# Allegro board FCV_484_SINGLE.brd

Outline 347.98 x 322.58 mm; copper layers: TOP, SIG1, SIG2, SIG3, BOTTOM. Coordinates in mm from the lower left corner of the outline.
Outline path: rectangle 0,0 347.98,322.58

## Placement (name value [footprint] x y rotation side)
U1  -  [22X22]  173.99 168.17 0 top

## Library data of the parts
U1 = 22X22_0

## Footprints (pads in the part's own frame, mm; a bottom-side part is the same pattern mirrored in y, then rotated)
22X22
  round 0.401 smd: A1(-8.4,8.4) A2(-7.6,8.4) A3(-6.8,8.4) A4(-5.999,8.4) A5(-5.199,8.4) A6(-4.399,8.4) A7(-3.599,8.4) A8(-2.799,8.4) A9(-1.999,8.4) A10(-1.199,8.4) A11(-0.399,8.4) A12(0.399,8.4) A13(1.199,8.4) A14(1.999,8.4) A15(2.799,8.4) A16(3.599,8.4) A17(4.399,8.4) A18(5.199,8.4) A19(5.999,8.4) A20(6.8,8.4) A21(7.6,8.4) A22(8.4,8.4) AA1(-8.4,-7.6) AA2(-7.6,-7.6) AA3(-6.8,-7.6) AA4(-5.999,-7.6) AA5(-5.199,-7.6) AA6(-4.399,-7.6) AA7(-3.599,-7.6) AA8(-2.799,-7.6) AA9(-1.999,-7.6) AA10(-1.199,-7.6) AA11(-0.399,-7.6) AA12(0.399,-7.6) AA13(1.199,-7.6) AA14(1.999,-7.6) AA15(2.799,-7.6) AA16(3.599,-7.6) AA17(4.399,-7.6) AA18(5.199,-7.6) AA19(5.999,-7.6) AA20(6.8,-7.6) AA21(7.6,-7.6) AA22(8.4,-7.6) AB1(-8.4,-8.4) AB2(-7.6,-8.4) AB3(-6.8,-8.4) AB4(-5.999,-8.4) AB5(-5.199,-8.4) AB6(-4.399,-8.4) AB7(-3.599,-8.4) AB8(-2.799,-8.4) AB9(-1.999,-8.4) AB10(-1.199,-8.4) AB11(-0.399,-8.4) AB12(0.399,-8.4) AB13(1.199,-8.4) AB14(1.999,-8.4) AB15(2.799,-8.4) AB16(3.599,-8.4) AB17(4.399,-8.4) AB18(5.199,-8.4) AB19(5.999,-8.4) AB20(6.8,-8.4) AB21(7.6,-8.4) AB22(8.4,-8.4) B1(-8.4,7.6) B2(-7.6,7.6) B3(-6.8,7.6) B4(-5.999,7.6) B5(-5.199,7.6) B6(-4.399,7.6) B7(-3.599,7.6) B8(-2.799,7.6) B9(-1.999,7.6) B10(-1.199,7.6) B11(-0.399,7.6) B12(0.399,7.6) B13(1.199,7.6) B14(1.999,7.6) B15(2.799,7.6) B16(3.599,7.6) B17(4.399,7.6) B18(5.199,7.6) B19(5.999,7.6) B20(6.8,7.6) B21(7.6,7.6) B22(8.4,7.6) C1(-8.4,6.8) C2(-7.6,6.8) C3(-6.8,6.8) C4(-5.999,6.8) C5(-5.199,6.8) C6(-4.399,6.8) C7(-3.599,6.8) C8(-2.799,6.8) C9(-1.999,6.8) C10(-1.199,6.8) C11(-0.399,6.8) C12(0.399,6.8) C13(1.199,6.8) C14(1.999,6.8) C15(2.799,6.8) C16(3.599,6.8) C17(4.399,6.8) C18(5.199,6.8) C19(5.999,6.8) C20(6.8,6.8) C21(7.6,6.8) C22(8.4,6.8) D1(-8.4,5.999) D2(-7.6,5.999) D3(-6.8,5.999) D4(-5.999,5.999) D5(-5.199,5.999) D6(-4.399,5.999) D7(-3.599,5.999) D8(-2.799,5.999) D9(-1.999,5.999) D10(-1.199,5.999) D11(-0.399,5.999) D12(0.399,5.999) D13(1.199,5.999) D14(1.999,5.999) D15(2.799,5.999) D16(3.599,5.999) D17(4.399,5.999) D18(5.199,5.999) D19(5.999,5.999) D20(6.8,5.999) D21(7.6,5.999) D22(8.4,5.999) E1(-8.4,5.199) E2(-7.6,5.199) E3(-6.8,5.199) E4(-5.999,5.199) E5(-5.199,5.199) E6(-4.399,5.199) E7(-3.599,5.199) E8(-2.799,5.199) E9(-1.999,5.199) E10(-1.199,5.199) E11(-0.399,5.199) E12(0.399,5.199) E13(1.199,5.199) E14(1.999,5.199) E15(2.799,5.199) E16(3.599,5.199) E17(4.399,5.199) E18(5.199,5.199) E19(5.999,5.199) E20(6.8,5.199) E21(7.6,5.199) E22(8.4,5.199) F1(-8.4,4.399) F2(-7.6,4.399) F3(-6.8,4.399) F4(-5.999,4.399) F5(-5.199,4.399) F6(-4.399,4.399) F7(-3.599,4.399) F8(-2.799,4.399) F9(-1.999,4.399) F10(-1.199,4.399) F11(-0.399,4.399) F12(0.399,4.399) F13(1.199,4.399) F14(1.999,4.399) F15(2.799,4.399) F16(3.599,4.399) F17(4.399,4.399) F18(5.199,4.399) F19(5.999,4.399) F20(6.8,4.399) F21(7.6,4.399) F22(8.4,4.399) G1(-8.4,3.599) G2(-7.6,3.599) G3(-6.8,3.599) G4(-5.999,3.599) G5(-5.199,3.599) G6(-4.399,3.599) G7(-3.599,3.599) G8(-2.799,3.599) G9(-1.999,3.599) G10(-1.199,3.599) G11(-0.399,3.599) G12(0.399,3.599) G13(1.199,3.599) G14(1.999,3.599) G15(2.799,3.599) G16(3.599,3.599) G17(4.399,3.599) G18(5.199,3.599) G19(5.999,3.599) G20(6.8,3.599) G21(7.6,3.599) G22(8.4,3.599) H1(-8.4,2.799) H2(-7.6,2.799) H3(-6.8,2.799) H4(-5.999,2.799) H5(-5.199,2.799) H6(-4.399,2.799) H7(-3.599,2.799) H8(-2.799,2.799) H9(-1.999,2.799) H10(-1.199,2.799) H11(-0.399,2.799) H12(0.399,2.799) H13(1.199,2.799) H14(1.999,2.799) H15(2.799,2.799) H16(3.599,2.799) H17(4.399,2.799) H18(5.199,2.799) H19(5.999,2.799) H20(6.8,2.799) H21(7.6,2.799) H22(8.4,2.799) J1(-8.4,1.999) J2(-7.6,1.999) J3(-6.8,1.999) J4(-5.999,1.999) J5(-5.199,1.999) J6(-4.399,1.999) J7(-3.599,1.999) J8(-2.799,1.999) J9(-1.999,1.999) J10(-1.199,1.999) J11(-0.399,1.999) J12(0.399,1.999) J13(1.199,1.999) J14(1.999,1.999) J15(2.799,1.999) J16(3.599,1.999) J17(4.399,1.999) J18(5.199,1.999) J19(5.999,1.999) J20(6.8,1.999) J21(7.6,1.999) J22(8.4,1.999) K1(-8.4,1.199) K2(-7.6,1.199) K3(-6.8,1.199) K4(-5.999,1.199) K5(-5.199,1.199) K6(-4.399,1.199) K7(-3.599,1.199) K8(-2.799,1.199) K9(-1.999,1.199) K10(-1.199,1.199) K11(-0.399,1.199) K12(0.399,1.199) K13(1.199,1.199) K14(1.999,1.199) K15(2.799,1.199) K16(3.599,1.199) K17(4.399,1.199) K18(5.199,1.199) K19(5.999,1.199) K20(6.8,1.199) K21(7.6,1.199) K22(8.4,1.199) L1(-8.4,0.399) L2(-7.6,0.399) L3(-6.8,0.399) L4(-5.999,0.399) L5(-5.199,0.399) L6(-4.399,0.399) L7(-3.599,0.399) L8(-2.799,0.399) L9(-1.999,0.399) L10(-1.199,0.399) L11(-0.399,0.399) L12(0.399,0.399) L13(1.199,0.399) L14(1.999,0.399) L15(2.799,0.399) L16(3.599,0.399) L17(4.399,0.399) L18(5.199,0.399) L19(5.999,0.399) L20(6.8,0.399) L21(7.6,0.399) L22(8.4,0.399) M1(-8.4,-0.399) M2(-7.6,-0.399) M3(-6.8,-0.399) M4(-5.999,-0.399) M5(-5.199,-0.399) M6(-4.399,-0.399) M7(-3.599,-0.399) M8(-2.799,-0.399) M9(-1.999,-0.399) M10(-1.199,-0.399) M11(-0.399,-0.399) M12(0.399,-0.399) M13(1.199,-0.399) M14(1.999,-0.399) M15(2.799,-0.399) M16(3.599,-0.399) M17(4.399,-0.399) M18(5.199,-0.399) M19(5.999,-0.399) M20(6.8,-0.399) M21(7.6,-0.399) M22(8.4,-0.399) N1(-8.4,-1.199) N2(-7.6,-1.199) N3(-6.8,-1.199) N4(-5.999,-1.199) N5(-5.199,-1.199) N6(-4.399,-1.199) N7(-3.599,-1.199) N8(-2.799,-1.199) N9(-1.999,-1.199) N10(-1.199,-1.199) N11(-0.399,-1.199) N12(0.399,-1.199) N13(1.199,-1.199) N14(1.999,-1.199) N15(2.799,-1.199) N16(3.599,-1.199) N17(4.399,-1.199) N18(5.199,-1.199) N19(5.999,-1.199) N20(6.8,-1.199) N21(7.6,-1.199) N22(8.4,-1.199) P1(-8.4,-1.999) P2(-7.6,-1.999) P3(-6.8,-1.999) P4(-5.999,-1.999) P5(-5.199,-1.999) P6(-4.399,-1.999) P7(-3.599,-1.999) P8(-2.799,-1.999) P9(-1.999,-1.999) P10(-1.199,-1.999) P11(-0.399,-1.999) P12(0.399,-1.999) P13(1.199,-1.999) P14(1.999,-1.999) P15(2.799,-1.999) P16(3.599,-1.999) P17(4.399,-1.999) P18(5.199,-1.999) P19(5.999,-1.999) P20(6.8,-1.999) P21(7.6,-1.999) P22(8.4,-1.999) R1(-8.4,-2.799) R2(-7.6,-2.799) R3(-6.8,-2.799) R4(-5.999,-2.799) R5(-5.199,-2.799) R6(-4.399,-2.799) R7(-3.599,-2.799) R8(-2.799,-2.799) R9(-1.999,-2.799) R10(-1.199,-2.799) R11(-0.399,-2.799) R12(0.399,-2.799) R13(1.199,-2.799) R14(1.999,-2.799) R15(2.799,-2.799) R16(3.599,-2.799) R17(4.399,-2.799) R18(5.199,-2.799) R19(5.999,-2.799) R20(6.8,-2.799) R21(7.6,-2.799) R22(8.4,-2.799) T1(-8.4,-3.599) T2(-7.6,-3.599) T3(-6.8,-3.599) T4(-5.999,-3.599) T5(-5.199,-3.599) T6(-4.399,-3.599) T7(-3.599,-3.599) T8(-2.799,-3.599) T9(-1.999,-3.599) T10(-1.199,-3.599) T11(-0.399,-3.599) T12(0.399,-3.599) T13(1.199,-3.599) T14(1.999,-3.599) T15(2.799,-3.599) T16(3.599,-3.599) T17(4.399,-3.599) T18(5.199,-3.599) T19(5.999,-3.599) T20(6.8,-3.599) T21(7.6,-3.599) T22(8.4,-3.599) U1(-8.4,-4.399) U2(-7.6,-4.399) U3(-6.8,-4.399) U4(-5.999,-4.399) U5(-5.199,-4.399) U6(-4.399,-4.399) U7(-3.599,-4.399) U8(-2.799,-4.399) U9(-1.999,-4.399) U10(-1.199,-4.399) U11(-0.399,-4.399) U12(0.399,-4.399) U13(1.199,-4.399) U14(1.999,-4.399) U15(2.799,-4.399) U16(3.599,-4.399) U17(4.399,-4.399) U18(5.199,-4.399) U19(5.999,-4.399) U20(6.8,-4.399) U21(7.6,-4.399) U22(8.4,-4.399) V1(-8.4,-5.199) V2(-7.6,-5.199) V3(-6.8,-5.199) V4(-5.999,-5.199) V5(-5.199,-5.199) V6(-4.399,-5.199) V7(-3.599,-5.199) V8(-2.799,-5.199) V9(-1.999,-5.199) V10(-1.199,-5.199) V11(-0.399,-5.199) V12(0.399,-5.199) V13(1.199,-5.199) V14(1.999,-5.199) V15(2.799,-5.199) V16(3.599,-5.199) V17(4.399,-5.199) V18(5.199,-5.199) V19(5.999,-5.199) V20(6.8,-5.199) V21(7.6,-5.199) V22(8.4,-5.199) W1(-8.4,-5.999) W2(-7.6,-5.999) W3(-6.8,-5.999) W4(-5.999,-5.999) W5(-5.199,-5.999) W6(-4.399,-5.999) W7(-3.599,-5.999) W8(-2.799,-5.999) W9(-1.999,-5.999) W10(-1.199,-5.999) W11(-0.399,-5.999) W12(0.399,-5.999) W13(1.199,-5.999) W14(1.999,-5.999) W15(2.799,-5.999) W16(3.599,-5.999) W17(4.399,-5.999) W18(5.199,-5.999) W19(5.999,-5.999) W20(6.8,-5.999) W21(7.6,-5.999) W22(8.4,-5.999) Y1(-8.4,-6.8) Y2(-7.6,-6.8) Y3(-6.8,-6.8) Y4(-5.999,-6.8) Y5(-5.199,-6.8) Y6(-4.399,-6.8) Y7(-3.599,-6.8) Y8(-2.799,-6.8) Y9(-1.999,-6.8) Y10(-1.199,-6.8) Y11(-0.399,-6.8) Y12(0.399,-6.8) Y13(1.199,-6.8) Y14(1.999,-6.8) Y15(2.799,-6.8) Y16(3.599,-6.8) Y17(4.399,-6.8) Y18(5.199,-6.8) Y19(5.999,-6.8) Y20(6.8,-6.8) Y21(7.6,-6.8) Y22(8.4,-6.8)

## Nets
VDD: U1.J13(VDD#J13) U1.K12(VDD#K12) U1.K14(VDD#K14) U1.K16(VDD#K16) U1.L11(VDD#L11) U1.L15(VDD#L15) U1.L17(VDD#L17) U1.M12(VDD#M12) U1.M14(VDD#M14) U1.M16(VDD#M16) U1.N11(VDD#N11) U1.N13(VDD#N13) U1.N15(VDD#N15) U1.N17(VDD#N17)
VDD18: U1.N14(VDD18#N14) U1.P10(VDD18#P10) U1.P12(VDD18#P12) U1.P14(VDD18#P14) U1.P16(VDD18#P16)
VDD25: U1.H8(VDD25#H8) U1.J17(VDD25#J17) U1.L13(VDD25#L13) U1.R9(VDD25#R9) U1.R17(VDD25#R17)
VDDA: U1.G21(VDDA#G21) U1.J21(VDDA#J21) U1.K19(VDDA#K19) U1.L21(VDDA#L21) U1.N21(VDDA#N21) U1.P19(VDDA#P19) U1.R21(VDDA#R21)
VDDA25: U1.J18(VDDA25#J18) U1.N18(VDDA25#N18)
VDDAUX2: U1.H11(VDDAUX2#H11) U1.H14(VDDAUX2#H14) U1.H16(VDDAUX2#H16) U1.J15(VDDAUX2#J15)
VDDAUX4: U1.F4(VDDAUX4#F4) U1.G1(VDDAUX4#G1) U1.K10(VDDAUX4#K10) U1.M10(VDDAUX4#M10) U1.N9(VDDAUX4#N9)
VDDI0: U1.AA9(VDDI0#AA9) U1.AB6(VDDI0#AB6) U1.U1(VDDI0#U1) U1.U11(VDDI0#U11) U1.V8(VDDI0#V8) U1.W5(VDDI0#W5) U1.Y2(VDDI0#Y2)
VDDI1: U1.AA19(VDDI1#AA19) U1.AB16(VDDI1#AB16) U1.T14(VDDI1#T14) U1.V18(VDDI1#V18) U1.W15(VDDI1#W15) U1.Y12(VDDI1#Y12) U1.Y22(VDDI1#Y22)
VDDI2: U1.A9(VDDI2#A9) U1.A19(VDDI2#A19) U1.B6(VDDI2#B6) U1.B16(VDDI2#B16) U1.C3(VDDI2#C3) U1.C13(VDDI2#C13) U1.C21(VDDI2#C21) U1.D10(VDDI2#D10) U1.E7(VDDI2#E7) U1.E17(VDDI2#E17) U1.F14(VDDI2#F14) U1.H13(VDDI2#H13) U1.H17(VDDI2#H17)
VDDI3: U1.G11(VDDI3#G11) U1.J11(VDDI3#J11)
VDDI4: U1.J5(VDDI4#J5) U1.K2(VDDI4#K2) U1.L9(VDDI4#L9) U1.M6(VDDI4#M6) U1.N3(VDDI4#N3) U1.R7(VDDI4#R7) U1.T4(VDDI4#T4)
VDDSREF: U1.L18(VDDSREF#L18) U1.R18(VDDSREF#R18)
VSS: U1.A1(VSS#A1) U1.A4(VSS#A4) U1.A14(VSS#A14) U1.A22(VSS#A22) U1.AA4(VSS#AA4) U1.AA14(VSS#AA14) U1.AB1(VSS#AB1) U1.AB11(VSS#AB11) U1.AB22(VSS#AB22) U1.B11(VSS#B11) U1.C8(VSS#C8) U1.C18(VSS#C18) U1.D5(VSS#D5) U1.D15(VSS#D15) U1.E2(VSS#E2) U1.E12(VSS#E12) U1.F9(VSS#F9) U1.G6(VSS#G6) U1.G16(VSS#G16) U1.H3(VSS#H3) U1.J10(VSS#J10) U1.J12(VSS#J12) U1.J14(VSS#J14) U1.J16(VSS#J16) U1.K7(VSS#K7) U1.K11(VSS#K11) U1.K13(VSS#K13) U1.K15(VSS#K15) U1.K17(VSS#K17) U1.L4(VSS#L4) U1.L10(VSS#L10) U1.L12(VSS#L12) U1.L14(VSS#L14) U1.L16(VSS#L16) U1.M1(VSS#M1) U1.M11(VSS#M11) U1.M13(VSS#M13) U1.M15(VSS#M15) U1.M17(VSS#M17) U1.N10(VSS#N10) U1.N12(VSS#N12) U1.N16(VSS#N16) U1.P5(VSS#P5) U1.P11(VSS#P11) U1.P13(VSS#P13) U1.P15(VSS#P15) U1.P17(VSS#P17) U1.R2(VSS#R2) U1.T9(VSS#T9) U1.U6(VSS#U6) U1.U16(VSS#U16) U1.V3(VSS#V3) U1.V13(VSS#V13) U1.W10(VSS#W10) U1.W20(VSS#W20) U1.Y7(VSS#Y7) U1.Y17(VSS#Y17)
VSSA: U1.E20(VSSA#E20) U1.E21(VSSA#E21) U1.E22(VSSA#E22) U1.F18(VSSA#F18) U1.F19(VSSA#F19) U1.F20(VSSA#F20) U1.G18(VSSA#G18) U1.G22(VSSA#G22) U1.H20(VSSA#H20) U1.J22(VSSA#J22) U1.K18(VSSA#K18) U1.K20(VSSA#K20) U1.L22(VSSA#L22) U1.M18(VSSA#M18) U1.M19(VSSA#M19) U1.M20(VSSA#M20) U1.N22(VSSA#N22) U1.P18(VSSA#P18) U1.P20(VSSA#P20) U1.R22(VSSA#R22) U1.T18(VSSA#T18) U1.T19(VSSA#T19) U1.T20(VSSA#T20) U1.U20(VSSA#U20) U1.U21(VSSA#U21) U1.U22(VSSA#U22)
IO-BANK0_1: U1.R10(IO-BANK0_1)
IO-BANK0_2: U1.R11(IO-BANK0_2)
IO-BANK0_3: U1.R12(IO-BANK0_3)
IO-BANK0_4: U1.T6(IO-BANK0_4)
IO-BANK0_5: U1.T7(IO-BANK0_5)
IO-BANK0_6: U1.T8(IO-BANK0_6)
IO-BANK0_7: U1.T10(IO-BANK0_7)
IO-BANK0_8: U1.T11(IO-BANK0_8)
IO-BANK0_9: U1.U2(IO-BANK0_9)
IO-BANK0_10: U1.U3(IO-BANK0_10)
IO-BANK0_11: U1.U4(IO-BANK0_11)
IO-BANK0_12: U1.U5(IO-BANK0_12)
IO-BANK0_13: U1.U7(IO-BANK0_13)
IO-BANK0_14: U1.U8(IO-BANK0_14)
IO-BANK0_15: U1.U9(IO-BANK0_15)
IO-BANK0_16: U1.U10(IO-BANK0_16)
IO-BANK0_17: U1.V1(IO-BANK0_17)
IO-BANK0_18: U1.V2(IO-BANK0_18)
IO-BANK0_19: U1.V4(IO-BANK0_19)
IO-BANK0_20: U1.V5(IO-BANK0_20)
IO-BANK0_21: U1.V6(IO-BANK0_21)
IO-BANK0_22: U1.V7(IO-BANK0_22)
IO-BANK0_23: U1.V9(IO-BANK0_23)
IO-BANK0_24: U1.V10(IO-BANK0_24)
IO-BANK0_25: U1.V11(IO-BANK0_25)
IO-BANK0_26: U1.W1(IO-BANK0_26)
IO-BANK0_27: U1.W2(IO-BANK0_27)
IO-BANK0_28: U1.W3(IO-BANK0_28)
IO-BANK0_29: U1.W4(IO-BANK0_29)
IO-BANK0_30: U1.W6(IO-BANK0_30)
IO-BANK0_31: U1.W7(IO-BANK0_31)
IO-BANK0_32: U1.W8(IO-BANK0_32)
IO-BANK0_33: U1.W9(IO-BANK0_33)
IO-BANK0_34: U1.W11(IO-BANK0_34)
IO-BANK0_35: U1.Y1(IO-BANK0_35)
IO-BANK0_36: U1.Y3(IO-BANK0_36)
IO-BANK0_37: U1.Y4(IO-BANK0_37)
IO-BANK0_38: U1.Y5(IO-BANK0_38)
IO-BANK0_39: U1.Y6(IO-BANK0_39)
IO-BANK0_40: U1.Y8(IO-BANK0_40)
IO-BANK0_41: U1.Y9(IO-BANK0_41)
IO-BANK0_42: U1.Y10(IO-BANK0_42)
IO-BANK0_43: U1.Y11(IO-BANK0_43)
IO-BANK0_44: U1.AA1(IO-BANK0_44)
IO-BANK0_45: U1.AA2(IO-BANK0_45)
IO-BANK0_46: U1.AA3(IO-BANK0_46)
IO-BANK0_47: U1.AA5(IO-BANK0_47)
IO-BANK0_48: U1.AA6(IO-BANK0_48)
IO-BANK0_49: U1.AA7(IO-BANK0_49)
IO-BANK0_50: U1.AA8(IO-BANK0_50)
IO-BANK0_51: U1.AA10(IO-BANK0_51)
IO-BANK0_52: U1.AA11(IO-BANK0_52)
IO-BANK0_53: U1.AB2(IO-BANK0_53)
IO-BANK0_54: U1.AB3(IO-BANK0_54)
IO-BANK0_55: U1.AB4(IO-BANK0_55)
IO-BANK0_56: U1.AB5(IO-BANK0_56)
IO-BANK0_57: U1.AB7(IO-BANK0_57)
IO-BANK0_58: U1.AB8(IO-BANK0_58)
IO-BANK0_59: U1.AB9(IO-BANK0_59)
IO-BANK0_60: U1.AB10(IO-BANK0_60)
IO-BANK1_1: U1.R13(IO-BANK1_1)
IO-BANK1_2: U1.R14(IO-BANK1_2)
IO-BANK1_3: U1.R15(IO-BANK1_3)
IO-BANK1_4: U1.R16(IO-BANK1_4)
IO-BANK1_5: U1.T12(IO-BANK1_5)
IO-BANK1_6: U1.T13(IO-BANK1_6)
IO-BANK1_7: U1.T15(IO-BANK1_7)
IO-BANK1_8: U1.T16(IO-BANK1_8)
IO-BANK1_9: U1.T17(IO-BANK1_9)
IO-BANK1_10: U1.U12(IO-BANK1_10)
IO-BANK1_11: U1.U13(IO-BANK1_11)
IO-BANK1_12: U1.U14(IO-BANK1_12)
IO-BANK1_13: U1.U15(IO-BANK1_13)
IO-BANK1_14: U1.U17(IO-BANK1_14)
IO-BANK1_15: U1.U18(IO-BANK1_15)
IO-BANK1_16: U1.U19(IO-BANK1_16)
IO-BANK1_17: U1.V12(IO-BANK1_17)
IO-BANK1_18: U1.V14(IO-BANK1_18)
IO-BANK1_19: U1.V15(IO-BANK1_19)
IO-BANK1_20: U1.V16(IO-BANK1_20)
IO-BANK1_21: U1.V17(IO-BANK1_21)
IO-BANK1_22: U1.V19(IO-BANK1_22)
IO-BANK1_23: U1.V20(IO-BANK1_23)
IO-BANK1_24: U1.V21(IO-BANK1_24)
IO-BANK1_25: U1.V22(IO-BANK1_25)
IO-BANK1_26: U1.W12(IO-BANK1_26)
IO-BANK1_27: U1.W13(IO-BANK1_27)
IO-BANK1_28: U1.W14(IO-BANK1_28)
IO-BANK1_29: U1.W16(IO-BANK1_29)
IO-BANK1_30: U1.W17(IO-BANK1_30)
IO-BANK1_31: U1.W18(IO-BANK1_31)
IO-BANK1_32: U1.W19(IO-BANK1_32)
IO-BANK1_33: U1.W21(IO-BANK1_33)
IO-BANK1_34: U1.W22(IO-BANK1_34)
IO-BANK1_35: U1.Y13(IO-BANK1_35)
IO-BANK1_36: U1.Y14(IO-BANK1_36)
IO-BANK1_37: U1.Y15(IO-BANK1_37)
IO-BANK1_38: U1.Y16(IO-BANK1_38)
IO-BANK1_39: U1.Y18(IO-BANK1_39)
IO-BANK1_40: U1.Y19(IO-BANK1_40)
IO-BANK1_41: U1.Y20(IO-BANK1_41)
IO-BANK1_42: U1.Y21(IO-BANK1_42)
IO-BANK1_43: U1.AA12(IO-BANK1_43)
IO-BANK1_44: U1.AA13(IO-BANK1_44)
IO-BANK1_45: U1.AA15(IO-BANK1_45)
IO-BANK1_46: U1.AA16(IO-BANK1_46)
IO-BANK1_47: U1.AA17(IO-BANK1_47)
IO-BANK1_48: U1.AA18(IO-BANK1_48)
IO-BANK1_49: U1.AA20(IO-BANK1_49)
IO-BANK1_50: U1.AA21(IO-BANK1_50)
IO-BANK1_51: U1.AA22(IO-BANK1_51)
IO-BANK1_52: U1.AB12(IO-BANK1_52)
IO-BANK1_53: U1.AB13(IO-BANK1_53)
IO-BANK1_54: U1.AB14(IO-BANK1_54)
IO-BANK1_55: U1.AB15(IO-BANK1_55)
IO-BANK1_56: U1.AB17(IO-BANK1_56)
IO-BANK1_57: U1.AB18(IO-BANK1_57)
IO-BANK1_58: U1.AB19(IO-BANK1_58)
IO-BANK1_59: U1.AB20(IO-BANK1_59)
IO-BANK1_60: U1.AB21(IO-BANK1_60)
IO-BANK2_1: U1.A2(IO-BANK2_1)
IO-BANK2_2: U1.A3(IO-BANK2_2)
IO-BANK2_3: U1.A5(IO-BANK2_3)
IO-BANK2_4: U1.A6(IO-BANK2_4)
IO-BANK2_5: U1.A7(IO-BANK2_5)
IO-BANK2_6: U1.A8(IO-BANK2_6)
IO-BANK2_7: U1.A10(IO-BANK2_7)
IO-BANK2_8: U1.A11(IO-BANK2_8)
IO-BANK2_9: U1.A12(IO-BANK2_9)
IO-BANK2_10: U1.A13(IO-BANK2_10)
IO-BANK2_11: U1.A15(IO-BANK2_11)
IO-BANK2_12: U1.A16(IO-BANK2_12)
IO-BANK2_13: U1.A17(IO-BANK2_13)
IO-BANK2_14: U1.A18(IO-BANK2_14)
IO-BANK2_15: U1.A20(IO-BANK2_15)
IO-BANK2_16: U1.A21(IO-BANK2_16)
IO-BANK2_17: U1.B1(IO-BANK2_17)
IO-BANK2_18: U1.B2(IO-BANK2_18)
IO-BANK2_19: U1.B3(IO-BANK2_19)
IO-BANK2_20: U1.B4(IO-BANK2_20)
IO-BANK2_21: U1.B5(IO-BANK2_21)
IO-BANK2_22: U1.B7(IO-BANK2_22)
IO-BANK2_23: U1.B8(IO-BANK2_23)
IO-BANK2_24: U1.B9(IO-BANK2_24)
IO-BANK2_25: U1.B10(IO-BANK2_25)
IO-BANK2_26: U1.B12(IO-BANK2_26)
IO-BANK2_27: U1.B13(IO-BANK2_27)
IO-BANK2_28: U1.B14(IO-BANK2_28)
IO-BANK2_29: U1.B15(IO-BANK2_29)
IO-BANK2_30: U1.B17(IO-BANK2_30)
IO-BANK2_31: U1.B18(IO-BANK2_31)
IO-BANK2_32: U1.B19(IO-BANK2_32)
IO-BANK2_33: U1.B20(IO-BANK2_33)
IO-BANK2_34: U1.B21(IO-BANK2_34)
IO-BANK2_35: U1.B22(IO-BANK2_35)
IO-BANK2_36: U1.C1(IO-BANK2_36)
IO-BANK2_37: U1.C2(IO-BANK2_37)
IO-BANK2_38: U1.C4(IO-BANK2_38)
IO-BANK2_39: U1.C5(IO-BANK2_39)
IO-BANK2_40: U1.C6(IO-BANK2_40)
IO-BANK2_41: U1.C7(IO-BANK2_41)
IO-BANK2_42: U1.C9(IO-BANK2_42)
IO-BANK2_43: U1.C10(IO-BANK2_43)
IO-BANK2_44: U1.C11(IO-BANK2_44)
IO-BANK2_45: U1.C12(IO-BANK2_45)
IO-BANK2_46: U1.C14(IO-BANK2_46)
IO-BANK2_47: U1.C15(IO-BANK2_47)
IO-BANK2_48: U1.C16(IO-BANK2_48)
IO-BANK2_49: U1.C17(IO-BANK2_49)
IO-BANK2_50: U1.C19(IO-BANK2_50)
IO-BANK2_51: U1.C20(IO-BANK2_51)
IO-BANK2_52: U1.C22(IO-BANK2_52)
IO-BANK2_53: U1.D3(IO-BANK2_53)
IO-BANK2_54: U1.D4(IO-BANK2_54)
IO-BANK2_55: U1.D6(IO-BANK2_55)
IO-BANK2_56: U1.D7(IO-BANK2_56)
IO-BANK2_57: U1.D8(IO-BANK2_57)
IO-BANK2_58: U1.D9(IO-BANK2_58)
IO-BANK2_59: U1.D11(IO-BANK2_59)
IO-BANK2_60: U1.D12(IO-BANK2_60)
IO-BANK2_61: U1.D13(IO-BANK2_61)
IO-BANK2_62: U1.D14(IO-BANK2_62)
IO-BANK2_63: U1.D16(IO-BANK2_63)
IO-BANK2_64: U1.D17(IO-BANK2_64)
IO-BANK2_65: U1.D18(IO-BANK2_65)
IO-BANK2_66: U1.D19(IO-BANK2_66)
IO-BANK2_67: U1.D20(IO-BANK2_67)
IO-BANK2_68: U1.D21(IO-BANK2_68)
IO-BANK2_69: U1.D22(IO-BANK2_69)
IO-BANK2_70: U1.E4(IO-BANK2_70)
IO-BANK2_71: U1.E5(IO-BANK2_71)
IO-BANK2_72: U1.E6(IO-BANK2_72)
IO-BANK2_73: U1.E8(IO-BANK2_73)
IO-BANK2_74: U1.E9(IO-BANK2_74)
IO-BANK2_75: U1.E10(IO-BANK2_75)
IO-BANK2_76: U1.E11(IO-BANK2_76)
IO-BANK2_77: U1.E13(IO-BANK2_77)
IO-BANK2_78: U1.E14(IO-BANK2_78)
IO-BANK2_79: U1.E15(IO-BANK2_79)
IO-BANK2_80: U1.E16(IO-BANK2_80)
IO-BANK2_81: U1.E18(IO-BANK2_81)
IO-BANK2_82: U1.E19(IO-BANK2_82)
IO-BANK2_83: U1.F10(IO-BANK2_83)
IO-BANK2_84: U1.F11(IO-BANK2_84)
IO-BANK2_85: U1.F12(IO-BANK2_85)
IO-BANK2_86: U1.F13(IO-BANK2_86)
IO-BANK2_87: U1.F15(IO-BANK2_87)
IO-BANK2_88: U1.F16(IO-BANK2_88)
IO-BANK2_89: U1.F17(IO-BANK2_89)
IO-BANK2_90: U1.G12(IO-BANK2_90)
IO-BANK2_91: U1.G13(IO-BANK2_91)
IO-BANK2_92: U1.G14(IO-BANK2_92)
IO-BANK2_93: U1.G15(IO-BANK2_93)
IO-BANK2_94: U1.G17(IO-BANK2_94)
IO-BANK2_95: U1.H12(IO-BANK2_95)
IO-BANK2_96: U1.H15(IO-BANK2_96)
IO-BANK4_1: U1.H1(IO-BANK4_1)
IO-BANK4_2: U1.H2(IO-BANK4_2)
IO-BANK4_3: U1.J1(IO-BANK4_3)
IO-BANK4_4: U1.J2(IO-BANK4_4)
IO-BANK4_5: U1.J3(IO-BANK4_5)
IO-BANK4_6: U1.J4(IO-BANK4_6)
IO-BANK4_7: U1.J6(IO-BANK4_7)
IO-BANK4_8: U1.J7(IO-BANK4_8)
IO-BANK4_9: U1.J8(IO-BANK4_9)
IO-BANK4_10: U1.J9(IO-BANK4_10)
IO-BANK4_11: U1.K1(IO-BANK4_11)
IO-BANK4_12: U1.K3(IO-BANK4_12)
IO-BANK4_13: U1.K4(IO-BANK4_13)
IO-BANK4_14: U1.K5(IO-BANK4_14)
IO-BANK4_15: U1.K6(IO-BANK4_15)
IO-BANK4_16: U1.K8(IO-BANK4_16)
IO-BANK4_17: U1.K9(IO-BANK4_17)
IO-BANK4_18: U1.L1(IO-BANK4_18)
IO-BANK4_19: U1.L2(IO-BANK4_19)
IO-BANK4_20: U1.L3(IO-BANK4_20)
IO-BANK4_21: U1.L5(IO-BANK4_21)
IO-BANK4_22: U1.L6(IO-BANK4_22)
IO-BANK4_23: U1.L7(IO-BANK4_23)
IO-BANK4_24: U1.L8(IO-BANK4_24)
IO-BANK4_25: U1.M2(IO-BANK4_25)
IO-BANK4_26: U1.M3(IO-BANK4_26)
IO-BANK4_27: U1.M4(IO-BANK4_27)
IO-BANK4_28: U1.M5(IO-BANK4_28)
IO-BANK4_29: U1.M7(IO-BANK4_29)
IO-BANK4_30: U1.M8(IO-BANK4_30)
IO-BANK4_31: U1.M9(IO-BANK4_31)
IO-BANK4_32: U1.N1(IO-BANK4_32)
IO-BANK4_33: U1.N2(IO-BANK4_33)
IO-BANK4_34: U1.N4(IO-BANK4_34)
IO-BANK4_35: U1.N5(IO-BANK4_35)
IO-BANK4_36: U1.N6(IO-BANK4_36)
IO-BANK4_37: U1.N7(IO-BANK4_37)
IO-BANK4_38: U1.N8(IO-BANK4_38)
IO-BANK4_39: U1.P1(IO-BANK4_39)
IO-BANK4_40: U1.P2(IO-BANK4_40)
IO-BANK4_41: U1.P3(IO-BANK4_41)
IO-BANK4_42: U1.P4(IO-BANK4_42)
IO-BANK4_43: U1.P6(IO-BANK4_43)
IO-BANK4_44: U1.P7(IO-BANK4_44)
IO-BANK4_45: U1.P8(IO-BANK4_45)
IO-BANK4_46: U1.P9(IO-BANK4_46)
IO-BANK4_47: U1.R1(IO-BANK4_47)
IO-BANK4_48: U1.R3(IO-BANK4_48)
IO-BANK4_49: U1.R4(IO-BANK4_49)
IO-BANK4_50: U1.R5(IO-BANK4_50)
IO-BANK4_51: U1.R6(IO-BANK4_51)
IO-BANK4_52: U1.R8(IO-BANK4_52)
IO-BANK4_53: U1.T1(IO-BANK4_53)
IO-BANK4_54: U1.T2(IO-BANK4_54)
IO-BANK4_55: U1.T3(IO-BANK4_55)
IO-BANK4_56: U1.T5(IO-BANK4_56)
IO-BANK5_1: U1.D1(IO-BANK5_1)
IO-BANK5_2: U1.D2(IO-BANK5_2)
IO-BANK5_3: U1.E1(IO-BANK5_3)
IO-BANK5_4: U1.E3(IO-BANK5_4)
IO-BANK5_5: U1.F1(IO-BANK5_5)
IO-BANK5_6: U1.F2(IO-BANK5_6)
IO-BANK5_7: U1.F3(IO-BANK5_7)
IO-BANK5_8: U1.F5(IO-BANK5_8)
IO-BANK5_9: U1.G2(IO-BANK5_9)
IO-BANK5_10: U1.G3(IO-BANK5_10)
IO-BANK5_11: U1.G4(IO-BANK5_11)
IO-BANK5_12: U1.G5(IO-BANK5_12)
JTAG-IO_1: U1.F6(JTAG-IO_1)
JTAG-IO_2: U1.F7(JTAG-IO_2)
JTAG-IO_3: U1.F8(JTAG-IO_3)
JTAG-IO_4: U1.G7(JTAG-IO_4)
JTAG-IO_5: U1.G8(JTAG-IO_5)
JTAG-IO_6: U1.G9(JTAG-IO_6)
JTAG-IO_7: U1.G10(JTAG-IO_7)
JTAG-IO_8: U1.H4(JTAG-IO_8)
JTAG-IO_9: U1.H5(JTAG-IO_9)
JTAG-IO_10: U1.H6(JTAG-IO_10)
JTAG-IO_11: U1.H7(JTAG-IO_11)
JTAG-IO_12: U1.H9(JTAG-IO_12)
JTAG-IO_13: U1.H10(JTAG-IO_13)
REFCLK0_1: U1.N19(REFCLK0_1)
REFCLK0_2: U1.N20(REFCLK0_2)
REFCLK1_1: U1.L19(REFCLK1_1)
REFCLK1_2: U1.L20(REFCLK1_2)
REFCLK2_1: U1.J19(REFCLK2_1)
REFCLK2_2: U1.J20(REFCLK2_2)
RX0_1: U1.R19(RX0_1)
RX0_2: U1.R20(RX0_2)
RX1_1: U1.M21(RX1_1)
RX1_2: U1.M22(RX1_2)
RX2_1: U1.K21(RX2_1)
RX2_2: U1.K22(RX2_2)
RX3_1: U1.G19(RX3_1)
RX3_2: U1.G20(RX3_2)
SERDES_VREF: U1.H18(SERDES_VREF#H18) U1.H19(SERDES_VREF#H19)
TX0_1: U1.T21(TX0_1)
TX0_2: U1.T22(TX0_2)
TX1_1: U1.P21(TX1_1)
TX1_2: U1.P22(TX1_2)
TX2_1: U1.H21(TX2_1)
TX2_2: U1.H22(TX2_2)
TX3_1: U1.F21(TX3_1)
TX3_2: U1.F22(TX3_2)

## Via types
v1: diameter 0.457, hole 0.254, TOP to BOTTOM, 365 vias

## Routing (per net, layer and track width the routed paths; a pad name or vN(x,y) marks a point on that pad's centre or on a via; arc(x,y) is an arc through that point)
VDD: length 7.9
  TOP w0.381: U1.K16 v1(177.99,169.77) ; U1.N15 v1(177.19,166.57) ; U1.L11 v1(173.19,168.97) ; U1.L15 v1(177.19,168.97) ; U1.N17 v1(178.79,166.57) ; U1.L17 v1(178.79,168.97) ; U1.K12 v1(174.79,169.77) ; U1.K14 v1(176.39,169.77) ; U1.M12 v1(174.79,167.37) ; U1.J13 v1(175.59,170.57) ; U1.N11 v1(173.19,166.57) ; U1.N13 v1(175.59,166.57) ; U1.M14 v1(176.39,167.37) ; U1.M16 v1(177.99,167.37)
VDD18: length 2.8
  TOP w0.381: U1.P16 v1(177.99,165.77) ; U1.P12 v1(174.79,165.77) ; U1.P10 v1(172.39,165.77) ; U1.P14 v1(176.39,165.77) ; U1.N14 v1(176.39,166.57)
VDD25: length 2.8
  TOP w0.381: U1.J17 v1(178.79,170.57) ; U1.R17 v1(178.79,164.97) ; U1.L13 v1(175.59,168.97) ; U1.R9 v1(171.59,164.97) ; U1.H8 v1(170.79,171.37)
VDDA: length 4
  TOP w0.127: U1.L21 v1(181.99,168.97)
  TOP w0.381: U1.K19 v1(180.39,169.77) ; U1.N21 v1(181.99,166.57) ; U1.R21 v1(181.99,164.97) ; U1.J21 v1(181.99,170.57) ; U1.P19 v1(180.39,165.77) ; U1.G21 v1(181.99,172.17)
VDDA25: length 1.1
  TOP w0.381: U1.N18 v1(179.59,166.57) ; U1.J18 v1(179.59,170.57)
VDDAUX2: length 2.3
  TOP w0.381: U1.J15 v1(177.19,170.57) ; U1.H16 v1(177.99,171.37) ; U1.H11 v1(173.19,171.37) ; U1.H14 v1(176.39,171.37)
VDDAUX4: length 3
  TOP w0.127: U1.F4 v1(167.59,172.97)
  TOP w0.381: U1.G1 v1(164.9,171.77) ; U1.M10 v1(172.39,167.37) ; U1.K10 v1(172.39,169.77) ; U1.N9 v1(171.59,166.57)
VDDI0: length 4.2
  TOP w0.127: U1.V8 v1(170.79,162.57)
  TOP w0.381: U1.U11 v1(173.19,163.37) ; U1.W5 v1(168.39,161.77) ; U1.Y2 v1(165.99,160.97) ; U1.AA9 v1(171.59,160.17) ; U1.AB6 v1(169.59,159.08) ; U1.U1 v1(164.9,163.77)
VDDI1: length 4.2
  TOP w0.381: U1.AA19 v1(180.39,160.17) ; U1.W15 v1(177.19,161.77) ; U1.Y12 v1(174.79,160.97) ; U1.V18 v1(179.59,162.57) ; U1.T14 v1(176.39,164.17) ; U1.Y22 v1(183.08,161.37) ; U1.AB16 v1(177.59,159.08)
VDDI2: length 7.6
  TOP w0.127: U1.C13 v1(175.59,175.37)
  TOP w0.381: U1.E17 v1(178.79,173.77) ; U1.A19 v1(179.99,177.27) ; U1.F14 v1(176.39,172.97) ; U1.B16 v1(177.99,176.17) ; U1.D10 v1(172.39,174.57) ; U1.A9 v1(171.99,177.27) ; U1.E7 v1(169.99,173.77) ; U1.H13 v1(175.59,171.37) ; U1.C21 v1(181.99,175.37) ; U1.B6 v1(169.19,176.17) ; U1.C3 v1(166.79,175.37) ; U1.H17 v1(178.79,171.37)
VDDI3: length 1.1
  TOP w0.381: U1.G11 v1(173.19,172.17) ; U1.J11 v1(173.19,170.57)
VDDI4: length 4
  TOP w0.127: U1.N3 v1(166.79,166.57)
  TOP w0.381: U1.L9 v1(171.59,168.97) ; U1.J5 v1(168.39,170.57) ; U1.M6 v1(169.19,167.37) ; U1.K2 v1(165.99,169.77) ; U1.T4 v1(167.59,164.17) ; U1.R7 v1(169.99,164.97)
VDDSREF: length 1.1
  TOP w0.381: U1.L18 v1(179.59,168.97) ; U1.R18 v1(179.59,164.97)
VSS: length 33.4
  TOP w0.127: U1.G16 v1(177.99,172.17) ; U1.Y17 v1(178.79,160.97) ; U1.W10 v1(172.39,161.77) ; U1.W20 v1(181.19,161.77)
  TOP w0.381: U1.N10 v1(172.39,166.57) ; U1.R2 v1(165.99,164.97) ; U1.T9 v1(171.59,164.17) ; U1.D15 v1(177.19,174.57) ; U1.L12 v1(174.79,168.97) ; U1.P15 v1(177.19,165.77) ; U1.M17 v1(178.79,167.37) ; U1.G6 v1(169.19,172.17) ; U1.U6 v1(169.19,163.37) ; U1.AB11 v1(173.59,159.08) ; U1.J16 v1(177.99,170.57) ; U1.E12 v1(174.79,173.77) ; U1.K15 v1(177.19,169.77) ; U1.AA14 v1(176.39,160.17) ; U1.F9 v1(171.59,172.97) ; U1.AB1 v1(164.9,159.77) ; U1.K7 v1(169.99,169.77) ; U1.V13 v1(175.59,162.57) ; U1.L10 v1(172.39,168.97) ; U1.AB22 v1(182.39,159.08) ; U1.D5 v1(168.39,174.57) ; U1.B11 v1(173.19,176.17) ; U1.H3 v1(166.79,171.37) ; U1.M11 v1(173.19,167.37) ; U1.P11 v1(173.19,165.77) ; U1.M1 v1(164.9,167.77) ; U1.P13 v1(175.59,165.77) ; U1.C8 v1(170.79,175.37) ; U1.Y7 v1(169.99,160.97) ; U1.N12 v1(174.79,166.57) ; U1.A22 v1(182.39,177.27) ; U1.J14 v1(176.39,170.57) ; U1.P17 v1(178.79,165.77) ; U1.E2 v1(165.99,173.77) ; U1.C18 v1(179.59,175.37) ; U1.M15 v1(177.19,167.37) ; U1.AA4 v1(167.59,160.17) ; U1.M13 v1(175.59,167.37) ; U1.J12 v1(174.79,170.57) ; U1.L14 v1(176.39,168.97) ; U1.U16 v1(177.99,163.37) ; U1.L16 v1(177.99,168.97) ; U1.K11 v1(173.19,169.77) ; U1.N16 v1(177.99,166.57) ; U1.K13 v1(175.59,169.77) ; U1.A4 v1(167.99,177.27) ; U1.A1 v1(165.59,177.27) ; U1.K17 v1(178.79,169.77) ; U1.V3 v1(166.79,162.57) ; U1.P5 v1(168.39,165.77) ; U1.A14 v1(175.99,177.27) ; U1.L4 v1(167.59,168.97) ; U1.J10 v1(172.39,170.57)
VSSA: length 15.6
  TOP w0.381: U1.H20 v1(181.19,171.37) ; U1.T19 v1(180.39,164.17) ; U1.K20 v1(181.19,169.77) ; U1.U21 v1(181.99,163.37) ; U1.U22 v1(183.08,163.77) ; U1.P20 v1(181.19,165.77) ; U1.E20 v1(181.19,173.77) ; U1.G22 v1(183.08,171.77) ; U1.P18 v1(179.59,165.77) ; U1.N22 v1(183.08,166.97) ; U1.T18 v1(179.59,164.17) ; U1.M20 v1(181.19,167.37) ; U1.R22 v1(183.08,165.37) ; U1.T20 v1(181.19,164.17) ; U1.M18 v1(179.59,167.37) ; U1.U20 v1(181.19,163.37) ; U1.F19 v1(180.39,172.97) ; U1.J22 v1(183.08,170.17) ; U1.K18 v1(179.59,169.77) ; U1.F18 v1(179.59,172.97) ; U1.E21 v1(181.99,173.77) ; U1.G18 v1(179.59,172.17) ; U1.F20 v1(181.19,172.97) ; U1.M19 v1(180.39,167.37) ; U1.L22 v1(183.08,168.57) ; U1.E22 v1(183.08,173.37)
IO-BANK0_1: length 6.6
  TOP w0.127: U1.R10 v1(172.39,164.97)
  SIG3 w0.127: 173.66,159.89 173.66,164.36 173.46,164.57 172.8,164.57 v1(172.39,164.97)
IO-BANK0_2: length 6.2
  TOP w0.127: U1.R11 v1(173.19,164.97)
  SIG3 w0.127: 174.02,159.92 174.02,164.57 173.61,164.97 v1(173.19,164.97)
IO-BANK0_3: length 6
  TOP w0.127: U1.R12 v1(174.79,164.97)
  SIG3 w0.127: 174.35,159.72 174.35,164.53 v1(174.79,164.97)
IO-BANK0_4: length 4.4
  TOP w0.127: U1.T6 v1(169.19,164.17)
  SIG3 w0.127: 165.56,163.78 168.8,163.78 v1(169.19,164.17)
IO-BANK0_5: length 5.3
  TOP w0.127: U1.T7 v1(169.99,164.17)
  SIG2 w0.127: 165.46,163.78 169.6,163.78 v1(169.99,164.17)
IO-BANK0_6: length 5
  TOP w0.127: U1.T8 v1(170.79,164.17)
  SIG3 w0.127: v1(170.79,164.17) 170.4,163.78 170.4,159.85
IO-BANK0_7: length 5.5
  TOP w0.127: U1.T10 v1(172.39,164.17)
  SIG3 w0.127: v1(172.39,164.17) 172.8,163.77 172.8,159.38
IO-BANK0_8: length 5.1
  TOP w0.127: U1.T11 v1(173.19,164.17)
  SIG2 w0.127: v1(173.19,164.17) 173.86,163.5 173.86,159.92
IO-BANK0_9: length 2.3
  TOP w0.127: 164.25,163.37 165.98,163.37 U1.U2
IO-BANK0_10: length 3
  TOP w0.127: U1.U3 v1(166.79,163.37)
  SIG1 w0.127: v1(166.79,163.37) 164.31,163.37
IO-BANK0_11: length 4.3
  TOP w0.127: U1.U4 v1(167.59,163.37)
  SIG1 w0.127: v1(167.59,163.37) 167.2,163.77 165.46,163.77 164.97,164.26 164.24,164.26
IO-BANK0_12: length 3.6
  TOP w0.127: U1.U5 v1(168.39,163.37)
  SIG2 w0.127: 165.51,162.97 167.98,162.97 v1(168.39,163.37)
IO-BANK0_13: length 6.4
  TOP w0.127: U1.U7 v1(169.99,163.37)
  SIG1 w0.127: v1(169.99,163.37) 169.58,162.97 164.31,162.97
IO-BANK0_14: length 4.2
  TOP w0.127: U1.U8 v1(170.79,163.37)
  SIG2 w0.127: 170.4,159.93 170.4,162.98 v1(170.79,163.37)
IO-BANK0_15: length 4.3
  TOP w0.127: U1.U9 v1(171.59,163.37)
  SIG2 w0.127: v1(171.59,163.37) 172,162.97 172,159.84
IO-BANK0_16: length 4.9
  TOP w0.127: U1.U10 v1(172.39,163.37)
  SIG2 w0.127: 173.61,159.92 173.61,162.71 173.36,162.97 172.8,162.97 v1(172.39,163.37)
IO-BANK0_17: length 1.2
  TOP w0.127: U1.V1 164.39,162.97
IO-BANK0_18: length 2.1
  TOP w0.127: U1.V2 166,162.58 164.41,162.58
IO-BANK0_19: length 3.7
  TOP w0.127: U1.V4 v1(167.59,162.57)
  SIG1 w0.127: 164.63,162.18 167.2,162.18 v1(167.59,162.57)
IO-BANK0_20: length 3.4
  TOP w0.127: U1.V5 v1(168.39,162.57)
  SIG2 w0.127: v1(168.39,162.57) 168,162.18 165.71,162.18
IO-BANK0_21: length 3.8
  TOP w0.127: U1.V6 v1(169.19,162.57)
  SIG2 w0.127: 168.8,159.47 168.8,162.18 v1(169.19,162.57)
IO-BANK0_22: length 3.4
  TOP w0.127: U1.V7 v1(169.99,162.57)
  SIG2 w0.127: 169.6,159.92 169.6,162.18 v1(169.99,162.57)
IO-BANK0_23: length 3.5
  TOP w0.127: U1.V9 v1(171.59,162.57)
  SIG2 w0.127: v1(171.59,162.57) 171.2,162.18 171.2,159.77
IO-BANK0_24: length 3.6
  TOP w0.127: U1.V10 v1(172.39,162.57)
  SIG2 w0.127: v1(172.39,162.57) 172.8,162.17 172.8,159.69
IO-BANK0_25: length 5
  TOP w0.127: U1.V11 v1(173.19,162.57)
  SIG1 w0.127: 174.07,158.52 174.07,159.89 173.61,160.35 173.61,162.15 v1(173.19,162.57)
IO-BANK0_26: length 1.2
  TOP w0.127: U1.W1 164.39,162.17
IO-BANK0_27: length 2.2
  TOP w0.127: 164.39,161.77 165.99,161.77 U1.W2
IO-BANK0_28: length 2.7
  TOP w0.127: U1.W3 v1(166.79,161.77)
  SIG1 w0.127: v1(166.79,161.77) 164.63,161.77
IO-BANK0_29: length 3.7
  TOP w0.127: U1.W4 v1(167.59,161.77)
  SIG1 w0.127: v1(167.59,161.77) 167.2,161.38 164.63,161.38
IO-BANK0_30: length 4.1
  TOP w0.127: U1.W6 v1(169.19,161.77)
  SIG1 w0.127: 168.78,158.45 168.78,161.37 v1(169.19,161.77)
IO-BANK0_31: length 4.3
  TOP w0.127: U1.W7 v1(169.99,161.77)
  SIG1 w0.127: v1(169.99,161.77) 169.6,161.38 169.6,159.92 170.05,159.46 170.05,158.42
IO-BANK0_32: length 4.1
  TOP w0.127: U1.W8 v1(170.79,161.77)
  SIG1 w0.127: 170.4,158.37 170.4,161.38 v1(170.79,161.77)
IO-BANK0_33: length 4.1
  TOP w0.127: U1.W9 v1(171.59,161.77)
  SIG1 w0.127: v1(171.59,161.77) 171.2,161.38 171.2,158.37
IO-BANK0_34: length 4
  TOP w0.127: U1.W11 v1(173.19,161.77)
  SIG1 w0.127: v1(173.19,161.77) 172.8,161.38 172.8,158.52
IO-BANK0_35: length 1.2
  TOP w0.127: U1.Y1 164.39,161.37
IO-BANK0_36: length 3
  TOP w0.381: U1.Y3 v1(166.79,160.97)
  SIG1 w0.127: v1(166.79,160.97) 166.79,158.57
IO-BANK0_37: length 3.2
  TOP w0.127: U1.Y4 v1(167.59,160.97)
  SIG1 w0.127: 167.13,158.57 167.13,160.52 v1(167.59,160.97)
IO-BANK0_38: length 3.1
  TOP w0.127: U1.Y5 v1(168.39,160.97)
  SIG1 w0.127: v1(168.39,160.97) 168.39,158.45
IO-BANK0_39: length 3.1
  TOP w0.127: U1.Y6 v1(169.19,160.97)
  SIG1 w0.127: v1(169.19,160.97) 169.19,158.45
IO-BANK0_40: length 3.2
  TOP w0.127: U1.Y8 v1(170.79,160.97)
  SIG1 w0.127: v1(170.79,160.97) 170.79,158.37
IO-BANK0_41: length 3.2
  TOP w0.127: U1.Y9 v1(171.59,160.97)
  SIG1 w0.127: 171.98,158.52 171.98,160.58 v1(171.59,160.97)
IO-BANK0_42: length 3
  TOP w0.127: U1.Y10 v1(172.39,160.97)
  SIG1 w0.127: v1(172.39,160.97) 172.39,158.52
IO-BANK0_43: length 3
  TOP w0.127: U1.Y11 v1(173.19,160.97)
  SIG1 w0.127: v1(173.19,160.97) 173.19,158.55
IO-BANK0_44: length 1.2
  TOP w0.127: U1.AA1 164.39,160.57
IO-BANK0_45: length 2.2
  TOP w0.127: 166,158.57 166,160.18 U1.AA2
IO-BANK0_46: length 2.2
  TOP w0.127: U1.AA3 166.8,160.18 166.8,158.57
IO-BANK0_47: length 2.2
  TOP w0.127: U1.AA5 168.4,160.18 168.4,158.57
IO-BANK0_48: length 2.1
  TOP w0.127: U1.AA6 169.18,160.16 169.18,158.63
IO-BANK0_49: length 2.2
  TOP w0.127: 170,158.57 170,160.18 U1.AA7
IO-BANK0_50: length 2.2
  TOP w0.127: 170.8,158.57 170.8,160.18 U1.AA8
IO-BANK0_51: length 2.2
  TOP w0.127: U1.AA10 172.4,160.18 172.4,158.57
IO-BANK0_52: length 2.2
  TOP w0.127: 173.2,158.55 173.2,160.18 U1.AA11
IO-BANK0_53: length 1.2
  TOP w0.127: U1.AB2 166.39,158.6
IO-BANK0_54: length 1.2
  TOP w0.127: U1.AB3 167.19,158.6
IO-BANK0_55: length 1.2
  TOP w0.127: U1.AB4 167.99,158.6
IO-BANK0_56: length 1.2
  TOP w0.127: U1.AB5 168.79,158.6
IO-BANK0_57: length 1.2
  TOP w0.127: U1.AB7 170.39,158.6
IO-BANK0_58: length 1.2
  TOP w0.127: U1.AB8 171.19,158.6
IO-BANK0_59: length 1.2
  TOP w0.127: U1.AB9 171.99,158.6
IO-BANK0_60: length 1.2
  TOP w0.127: U1.AB10 172.79,158.6
IO-BANK1_1: length 6.3
  TOP w0.127: U1.R13 v1(175.59,164.97)
  SIG3 w0.127: 175.98,159.44 175.98,164.58 v1(175.59,164.97)
IO-BANK1_2: length 6.3
  TOP w0.127: U1.R14 v1(176.39,164.97)
  SIG3 w0.127: v1(176.39,164.97) 176.78,164.58 176.78,159.44
IO-BANK1_3: length 6.2
  TOP w0.127: U1.R15 v1(177.19,164.97)
  SIG3 w0.127: 182.68,164.58 177.58,164.58 v1(177.19,164.97)
IO-BANK1_4: length 5.1
  TOP w0.127: U1.R16 v1(177.99,164.97)
  SIG3 w0.127: 182.38,165.37 178.38,165.37 v1(177.99,164.97)
IO-BANK1_5: length 4.8
  TOP w0.127: U1.T12 v1(174.79,164.17)
  SIG2 w0.127: 174.14,160.25 174.14,163.53 v1(174.79,164.17)
IO-BANK1_6: length 5.3
  TOP w0.127: U1.T13 v1(175.59,164.17)
  SIG3 w0.127: v1(175.59,164.17) 175.2,163.78 175.2,159.59
IO-BANK1_7: length 5.8
  TOP w0.127: U1.T15 v1(177.19,164.17)
  SIG3 w0.127: v1(177.19,164.17) 177.58,163.78 182.3,163.78
IO-BANK1_8: length 5.1
  TOP w0.127: U1.T16 v1(177.99,164.17)
  SIG2 w0.127: 182.4,164.57 178.38,164.57 v1(177.99,164.17)
IO-BANK1_9: length 4.3
  TOP w0.127: U1.T17 v1(178.79,164.17)
  SIG2 w0.127: 182.36,163.77 179.2,163.77 v1(178.79,164.17)
IO-BANK1_10: length 3.8
  TOP w0.127: U1.U12 v1(174.79,163.37)
  SIG2 w0.127: v1(174.79,163.37) 174.4,162.98 174.4,160.27
IO-BANK1_11: length 3.9
  TOP w0.127: U1.U13 v1(175.59,163.37)
  SIG2 w0.127: v1(175.59,163.37) 175.2,162.98 175.2,160.2
IO-BANK1_12: length 3.8
  TOP w0.127: U1.U14 v1(176.39,163.37)
  SIG2 w0.127: v1(176.39,163.37) 176.78,162.98 176.78,160.27
IO-BANK1_13: length 5.6
  TOP w0.127: U1.U15 v1(177.19,163.37)
  SIG3 w0.127: v1(177.19,163.37) 177.58,162.98 177.58,159.93 178.05,159.46 178.05,158.65
IO-BANK1_14: length 4.4
  TOP w0.127: U1.U17 v1(178.79,163.37)
  SIG2 w0.127: 182.5,162.97 179.2,162.97 v1(178.79,163.37)
IO-BANK1_15: length 4.8
  TOP w0.127: U1.U18 v1(179.59,163.37)
  SIG1 w0.127: v1(179.59,163.37) 179.98,163.77 182.38,163.77 182.8,163.35 183.52,163.35
IO-BANK1_16: length 3.8
  TOP w0.127: U1.U19 v1(180.39,163.37)
  SIG1 w0.127: 183.46,162.98 180.78,162.98 v1(180.39,163.37)
IO-BANK1_17: length 4.9
  TOP w0.127: U1.V12 v1(174.79,162.57)
  SIG1 w0.127: 174.45,158.62 174.45,159.89 174.14,160.2 174.14,161.92 v1(174.79,162.57)
IO-BANK1_18: length 3.1
  TOP w0.127: U1.V14 v1(176.39,162.57)
  SIG2 w0.127: v1(176.39,162.57) 176,162.18 176,160.25
IO-BANK1_19: length 3.2
  TOP w0.127: U1.V15 v1(177.19,162.57)
  SIG2 w0.127: v1(177.19,162.57) 177.6,162.17 177.6,160.15
IO-BANK1_20: length 3.3
  TOP w0.127: U1.V16 v1(177.99,162.57)
  SIG2 w0.127: 178.4,160.05 178.4,162.17 v1(177.99,162.57)
IO-BANK1_21: length 3.2
  TOP w0.127: U1.V17 v1(178.79,162.57)
  SIG2 w0.127: 179.2,160.07 179.2,162.17 v1(178.79,162.57)
IO-BANK1_22: length 3.8
  TOP w0.127: U1.V19 v1(180.39,162.57)
  SIG1 w0.127: v1(180.39,162.57) 180.78,162.18 183.46,162.18
IO-BANK1_23: length 2.8
  TOP w0.127: U1.V20 v1(181.19,162.57)
  SIG1 w0.127: v1(181.19,162.57) 183.46,162.57
IO-BANK1_24: length 2.1
  TOP w0.127: 183.49,162.58 181.98,162.58 U1.V21
IO-BANK1_25: length 1.1
  TOP w0.127: U1.V22 183.48,162.97
IO-BANK1_26: length 4
  TOP w0.127: U1.W12 v1(174.79,161.77)
  SIG1 w0.127: 174.7,158.62 174.7,160 174.4,160.3 174.4,161.38 v1(174.79,161.77)
IO-BANK1_27: length 3.9
  TOP w0.127: U1.W13 v1(175.59,161.77)
  SIG1 w0.127: v1(175.59,161.77) 175.2,161.38 175.2,158.65
IO-BANK1_28: length 3.9
  TOP w0.127: U1.W14 v1(176.39,161.77)
  SIG1 w0.127: v1(176.39,161.77) 176,161.38 176,158.65
IO-BANK1_29: length 4
  TOP w0.127: U1.W16 v1(177.99,161.77)
  SIG1 w0.127: v1(177.99,161.77) 177.6,161.38 177.6,160.25 178.1,159.74 178.1,158.72
IO-BANK1_30: length 3.9
  TOP w0.127: U1.W17 v1(178.79,161.77)
  SIG1 w0.127: v1(178.79,161.77) 178.4,161.38 178.4,160.51 178.79,160.11 178.79,158.75
IO-BANK1_31: length 3.8
  TOP w0.127: U1.W18 v1(179.59,161.77)
  SIG1 w0.127: 179.2,158.7 179.2,161.38 v1(179.59,161.77)
IO-BANK1_32: length 3.8
  TOP w0.127: U1.W19 v1(180.39,161.77)
  SIG1 w0.127: 179.98,158.7 179.98,161.37 v1(180.39,161.77)
IO-BANK1_33: length 2.1
  TOP w0.127: 183.52,161.78 181.98,161.78 U1.W21
IO-BANK1_34: length 1.1
  TOP w0.127: U1.W22 183.48,162.17
IO-BANK1_35: length 2.9
  TOP w0.127: U1.Y13 v1(175.59,160.97)
  SIG1 w0.127: v1(175.59,160.97) 175.59,158.65
IO-BANK1_36: length 3.1
  TOP w0.127: U1.Y14 v1(176.39,160.97)
  SIG1 w0.127: 176.78,158.62 176.78,160.58 v1(176.39,160.97)
IO-BANK1_37: length 2.9
  TOP w0.127: U1.Y15 v1(177.19,160.97)
  SIG1 w0.127: v1(177.19,160.97) 177.19,158.62
IO-BANK1_38: length 3
  TOP w0.127: U1.Y16 v1(177.99,160.97)
  SIG1 w0.127: v1(177.99,160.97) 177.99,160.34 178.38,159.94 178.38,158.75
IO-BANK1_39: length 2.8
  TOP w0.127: U1.Y18 v1(179.59,160.97)
  SIG1 w0.127: v1(179.59,160.97) 179.59,158.7
IO-BANK1_40: length 3
  TOP w0.127: U1.Y19 v1(180.39,160.97)
  SIG1 w0.127: 180.78,158.7 180.78,160.58 v1(180.39,160.97)
IO-BANK1_41: length 2.8
  TOP w0.127: U1.Y20 v1(181.19,160.97)
  SIG1 w0.127: v1(181.19,160.97) 181.19,158.7
IO-BANK1_42: length 2.1
  TOP w0.127: U1.Y21 181.98,160.98 183.52,160.98
IO-BANK1_43: length 2.2
  TOP w0.127: U1.AA12 174.8,160.16 174.8,158.57
IO-BANK1_44: length 2.2
  TOP w0.127: 175.6,158.57 175.6,160.16 U1.AA13
IO-BANK1_45: length 2.1
  TOP w0.127: 177.19,158.6 177.19,160.17 U1.AA15
IO-BANK1_46: length 2.2
  TOP w0.127: U1.AA16 177.98,160.18 177.98,158.52
IO-BANK1_47: length 2.2
  TOP w0.127: U1.AA17 178.8,160.16 178.8,158.57
IO-BANK1_48: length 2.2
  TOP w0.127: 179.6,158.57 179.6,160.16 U1.AA18
IO-BANK1_49: length 2.2
  TOP w0.127: 181.2,158.57 181.2,160.16 U1.AA20
IO-BANK1_50: length 2.1
  TOP w0.127: 183.56,160.16 182,160.16 U1.AA21
IO-BANK1_51: length 1.2
  TOP w0.127: U1.AA22 183.56,160.57
IO-BANK1_52: length 1.1
  TOP w0.127: U1.AB12 174.39,158.68
IO-BANK1_53: length 1.1
  TOP w0.127: U1.AB13 175.19,158.68
IO-BANK1_54: length 1.1
  TOP w0.127: U1.AB14 175.99,158.72
IO-BANK1_55: length 1.1
  TOP w0.127: U1.AB15 176.79,158.68
IO-BANK1_56: length 1.1
  TOP w0.127: U1.AB17 178.39,158.68
IO-BANK1_57: length 1.1
  TOP w0.127: U1.AB18 179.19,158.68
IO-BANK1_58: length 1.1
  TOP w0.127: U1.AB19 179.99,158.63
IO-BANK1_59: length 1.1
  TOP w0.127: U1.AB20 180.79,158.68
IO-BANK1_60: length 1.1
  TOP w0.127: U1.AB21 181.59,158.68
IO-BANK2_1: length 1.3
  TOP w0.127: U1.A2 166.39,177.88
IO-BANK2_2: length 1.3
  TOP w0.127: U1.A3 167.19,177.88
IO-BANK2_3: length 1.3
  TOP w0.127: U1.A5 168.79,177.88
IO-BANK2_4: length 1.3
  TOP w0.127: U1.A6 169.59,177.88
IO-BANK2_5: length 1.3
  TOP w0.127: U1.A7 170.39,177.88
IO-BANK2_6: length 1.3
  TOP w0.127: U1.A8 171.19,177.88
IO-BANK2_7: length 1.3
  TOP w0.127: U1.A10 172.79,177.88
IO-BANK2_8: length 1.3
  TOP w0.127: U1.A11 173.59,177.86
IO-BANK2_9: length 1.3
  TOP w0.127: U1.A12 174.39,177.88
IO-BANK2_10: length 1.3
  TOP w0.127: U1.A13 175.19,177.88
IO-BANK2_11: length 1.3
  TOP w0.127: U1.A15 176.79,177.88
IO-BANK2_12: length 1.3
  TOP w0.127: U1.A16 177.59,177.88
IO-BANK2_13: length 1.3
  TOP w0.127: U1.A17 178.39,177.88
IO-BANK2_14: length 1.3
  TOP w0.127: U1.A18 179.19,177.88
IO-BANK2_15: length 1.3
  TOP w0.127: U1.A20 180.79,177.88
IO-BANK2_16: length 1.3
  TOP w0.127: U1.A21 181.59,177.86
IO-BANK2_17: length 1.2
  TOP w0.127: U1.B1 164.39,175.77
IO-BANK2_18: length 2.2
  TOP w0.127: U1.B2 165.99,176.17 164.39,176.17
IO-BANK2_19: length 2.3
  TOP w0.127: 166.8,177.88 166.8,176.16 U1.B3
IO-BANK2_20: length 2.3
  TOP w0.127: U1.B4 167.6,176.17 167.6,177.88
IO-BANK2_21: length 2.3
  TOP w0.127: U1.B5 168.4,176.16 168.4,177.88
IO-BANK2_22: length 2.3
  TOP w0.127: 170,177.88 170,176.16 U1.B7
IO-BANK2_23: length 2.3
  TOP w0.127: 170.8,177.88 170.8,176.16 U1.B8
IO-BANK2_24: length 2.3
  TOP w0.127: U1.B9 171.6,176.16 171.6,176.41 171.6,176.41 171.6,176.74 171.6,176.74 171.6,177.06 171.57,177.09 171.57,177.88
IO-BANK2_25: length 2.3
  TOP w0.127: 172.41,177.88 172.41,177.09 172.39,177.07 172.39,176.17 U1.B10
IO-BANK2_26: length 2.3
  TOP w0.127: 174,177.93 174,176.16 U1.B12
IO-BANK2_27: length 2.3
  TOP w0.127: 174.8,177.88 174.8,176.16 U1.B13
IO-BANK2_28: length 2.3
  TOP w0.127: 175.6,177.88 175.6,176.17 U1.B14
IO-BANK2_29: length 2.3
  TOP w0.127: 176.4,177.88 176.4,176.16 U1.B15
IO-BANK2_30: length 2.3
  TOP w0.127: U1.B17 178.8,176.18 178.8,177.9
IO-BANK2_31: length 2.3
  TOP w0.127: U1.B18 179.6,176.18 179.6,177.87
IO-BANK2_32: length 2.3
  TOP w0.127: 180.4,177.89 180.4,176.18 U1.B19
IO-BANK2_33: length 2.3
  TOP w0.127: U1.B20 181.18,176.16 181.18,177.9
IO-BANK2_34: length 2.7
  TOP w0.127: 184.15,176.17 181.99,176.17 U1.B21
IO-BANK2_35: length 1.3
  TOP w0.127: U1.B22 183.7,175.77
IO-BANK2_36: length 1.2
  TOP w0.127: U1.C1 164.39,174.97
IO-BANK2_37: length 2.2
  TOP w0.127: U1.C2 165.99,175.37 164.39,175.37
IO-BANK2_38: length 1.9
  TOP w0.127: U1.C4 v1(167.59,175.37)
  SIG1 w0.127: v1(167.59,175.37) 167.59,176.68
IO-BANK2_39: length 1.9
  TOP w0.127: U1.C5 v1(168.39,175.37)
  SIG1 w0.127: v1(168.39,175.37) 168.39,176.67
IO-BANK2_40: length 2.1
  TOP w0.127: U1.C6 v1(169.19,175.37)
  SIG1 w0.127: 168.73,176.68 168.73,175.83 v1(169.19,175.37)
IO-BANK2_41: length 1.9
  TOP w0.127: U1.C7 v1(169.99,175.37)
  SIG1 w0.127: v1(169.99,175.37) 169.99,176.75
IO-BANK2_42: length 1.8
  TOP w0.127: U1.C9 v1(171.59,175.37)
  SIG1 w0.127: v1(171.59,175.37) 171.59,176.62
IO-BANK2_43: length 1.8
  TOP w0.127: U1.C10 v1(172.39,175.37)
  SIG1 w0.127: v1(172.39,175.37) 172.39,176.63
IO-BANK2_44: length 2.2
  TOP w0.127: U1.C11 v1(173.19,175.37)
  SIG1 w0.127: v1(173.19,175.37) 173.63,175.82 173.63,176.81
IO-BANK2_45: length 2.1
  TOP w0.127: U1.C12 v1(174.79,175.37)
  SIG1 w0.127: v1(174.79,175.37) 174.79,176.9
IO-BANK2_46: length 1.7
  TOP w0.127: U1.C14 v1(176.39,175.37)
  SIG1 w0.127: v1(176.39,175.37) 176.39,176.52
IO-BANK2_47: length 1.7
  TOP w0.127: U1.C15 v1(177.19,175.37)
  SIG1 w0.127: v1(177.19,175.37) 177.19,176.5
IO-BANK2_48: length 2.1
  TOP w0.127: U1.C16 v1(177.99,175.37)
  SIG1 w0.127: 178.38,176.71 178.38,175.77 v1(177.99,175.37)
IO-BANK2_49: length 2
  TOP w0.127: U1.C17 v1(178.79,175.37)
  SIG1 w0.127: v1(178.79,175.37) 178.79,176.78
IO-BANK2_50: length 2.8
  TOP w0.127: U1.C19 v1(180.39,175.37)
  SIG1 w0.127: v1(180.39,175.37) 180.78,174.98 182.5,174.98
IO-BANK2_51: length 2.3
  TOP w0.381: U1.C20 v1(181.19,175.37)
  SIG1 w0.127: 182.7,175.82 181.64,175.82 v1(181.19,175.37)
IO-BANK2_52: length 1.3
  TOP w0.127: U1.C22 183.7,174.97
IO-BANK2_53: length 2.7
  TOP w0.127: U1.D3 v1(166.79,174.57)
  SIG1 w0.127: v1(166.79,174.57) 164.62,174.57
IO-BANK2_54: length 3.7
  TOP w0.127: U1.D4 v1(167.59,174.57)
  SIG1 w0.127: v1(167.59,174.57) 167.18,174.98 164.62,174.98
IO-BANK2_55: length 2.9
  TOP w0.127: U1.D6 v1(169.19,174.57)
  SIG3 w0.127: v1(169.19,174.57) 168.8,174.97 168.8,176.77
IO-BANK2_56: length 2.9
  TOP w0.127: U1.D7 v1(169.99,174.57)
  SIG1 w0.127: v1(169.99,174.57) 169.6,174.97 169.6,176.71
IO-BANK2_57: length 2.7
  TOP w0.127: U1.D8 v1(170.79,174.57)
  SIG1 w0.127: v1(170.79,174.57) 171.18,174.97 171.18,176.54
IO-BANK2_58: length 2.8
  TOP w0.127: U1.D9 v1(171.59,174.57)
  SIG1 w0.127: v1(171.59,174.57) 171.98,174.97 171.98,176.61
IO-BANK2_59: length 2.8
  TOP w0.127: U1.D11 v1(173.19,174.57)
  SIG1 w0.127: 172.8,176.68 172.8,174.97 v1(173.19,174.57)
IO-BANK2_60: length 3
  TOP w0.127: U1.D12 v1(174.79,174.57)
  SIG1 w0.127: v1(174.79,174.57) 174.37,174.99 174.37,176.83
IO-BANK2_61: length 3
  TOP w0.127: U1.D13 v1(175.59,174.57)
  SIG1 w0.127: 175.2,176.89 175.2,174.97 v1(175.59,174.57)
IO-BANK2_62: length 2.7
  TOP w0.127: U1.D14 v1(176.39,174.57)
  SIG1 w0.127: v1(176.39,174.57) 176,174.97 176,176.58
IO-BANK2_63: length 2.6
  TOP w0.127: U1.D16 v1(177.99,174.57)
  SIG1 w0.127: 177.6,176.48 177.6,174.97 v1(177.99,174.57)
IO-BANK2_64: length 2.9
  TOP w0.127: U1.D17 v1(178.79,174.57)
  SIG1 w0.127: 179.18,176.72 179.18,174.97 v1(178.79,174.57)
IO-BANK2_65: length 2.6
  TOP w0.127: U1.D18 v1(179.59,174.57)
  SIG1 w0.127: 179.98,176.45 179.98,174.97 v1(179.59,174.57)
IO-BANK2_66: length 2.9
  TOP w0.127: U1.D19 v1(180.39,174.57)
  SIG1 w0.127: 182.58,174.17 180.8,174.17 v1(180.39,174.57)
IO-BANK2_67: length 1.6
  TOP w0.127: U1.D20 v1(181.19,174.57)
  SIG1 w0.127: v1(181.19,174.57) 182.27,174.57
IO-BANK2_68: length 2.3
  TOP w0.127: U1.D21 181.98,174.56 183.69,174.56
IO-BANK2_69: length 0.9
  TOP w0.127: U1.D22 183.33,174.17
IO-BANK2_70: length 3.9
  TOP w0.127: U1.E4 v1(167.59,173.77)
  SIG1 w0.127: 164.38,173.38 167.2,173.38 v1(167.59,173.77)
IO-BANK2_71: length 3.6
  TOP w0.127: U1.E5 v1(168.39,173.77)
  SIG2 w0.127: v1(168.39,173.77) 168,174.17 168,176.66
IO-BANK2_72: length 3.6
  TOP w0.127: U1.E6 v1(169.19,173.77)
  SIG2 w0.127: 168.8,176.64 168.8,174.17 v1(169.19,173.77)
IO-BANK2_73: length 3.7
  TOP w0.127: U1.E8 v1(170.79,173.77)
  SIG2 w0.127: v1(170.79,173.77) 170.4,174.17 170.4,176.73
IO-BANK2_74: length 3.7
  TOP w0.127: U1.E9 v1(171.59,173.77)
  SIG2 w0.127: v1(171.59,173.77) 171.2,174.17 171.2,176.76
IO-BANK2_75: length 3.7
  TOP w0.127: U1.E10 v1(172.39,173.77)
  SIG2 w0.127: 172,176.76 172,174.17 v1(172.39,173.77)
IO-BANK2_76: length 3.9
  TOP w0.127: U1.E11 v1(173.19,173.77)
  SIG1 w0.127: v1(173.19,173.77) 173.94,174.52 173.94,176.83
IO-BANK2_77: length 3.9
  TOP w0.127: U1.E13 v1(175.59,173.77)
  SIG2 w0.127: v1(175.59,173.77) 175.2,174.17 175.2,176.91
IO-BANK2_78: length 3.6
  TOP w0.127: U1.E14 v1(176.39,173.77)
  SIG2 w0.127: 176,176.61 176,174.17 v1(176.39,173.77)
IO-BANK2_79: length 3.5
  TOP w0.127: U1.E15 v1(177.19,173.77)
  SIG2 w0.127: v1(177.19,173.77) 176.8,174.17 176.8,176.58
IO-BANK2_80: length 3.5
  TOP w0.127: U1.E16 v1(177.99,173.77)
  SIG2 w0.127: 177.58,176.54 177.58,174.18 v1(177.99,173.77)
IO-BANK2_81: length 3.7
  TOP w0.127: U1.E18 v1(179.59,173.77)
  SIG2 w0.127: 179.98,176.76 179.98,174.17 v1(179.59,173.77)
IO-BANK2_82: length 2.6
  TOP w0.127: U1.E19 v1(180.39,173.77)
  SIG1 w0.127: v1(180.39,173.77) 180.78,173.38 182.3,173.38
IO-BANK2_83: length 4.3
  TOP w0.127: U1.F10 v1(172.39,172.97)
  SIG2 w0.127: v1(172.39,172.97) 172.78,173.37 172.78,176.52
IO-BANK2_84: length 4.7
  TOP w0.127: U1.F11 v1(173.19,172.97)
  SIG2 w0.127: v1(173.19,172.97) 173.63,173.42 173.63,176.89
IO-BANK2_85: length 4.6
  TOP w0.127: U1.F12 v1(174.79,172.97)
  SIG2 w0.127: v1(174.79,172.97) 174.4,173.37 174.4,176.86
IO-BANK2_86: length 4.2
  TOP w0.127: U1.F13 v1(175.59,172.97)
  SIG3 w0.127: v1(175.59,172.97) 175.98,173.37 175.98,176.47
IO-BANK2_87: length 4.5
  TOP w0.127: U1.F15 v1(177.19,172.97)
  SIG3 w0.127: v1(177.19,172.97) 177.58,173.37 177.58,176.76
IO-BANK2_88: length 4.4
  TOP w0.127: U1.F16 v1(177.99,172.97)
  SIG2 w0.127: 178.38,176.61 178.38,173.37 v1(177.99,172.97)
IO-BANK2_89: length 4.6
  TOP w0.127: U1.F17 v1(178.79,172.97)
  SIG2 w0.127: v1(178.79,172.97) 179.18,173.37 179.18,176.81
IO-BANK2_90: length 5.5
  TOP w0.127: U1.G12 v1(174.79,172.17)
  SIG2 w0.127: v1(174.79,172.17) 174.14,172.82 174.14,176.86
IO-BANK2_91: length 5.1
  TOP w0.127: U1.G13 v1(175.59,172.17)
  SIG3 w0.127: v1(175.59,172.17) 175.2,172.57 175.2,176.58
IO-BANK2_92: length 5.2
  TOP w0.127: U1.G14 v1(176.39,172.17)
  SIG3 w0.127: 176.8,176.68 176.8,172.58 v1(176.39,172.17)
IO-BANK2_93: length 5.9
  TOP w0.127: U1.G15 v1(177.19,172.17)
  SIG2 w0.127: v1(177.19,172.17) 177.6,171.77 182.33,171.77
IO-BANK2_94: length 4.4
  TOP w0.127: U1.G17 v1(178.79,172.17)
  SIG1 w0.127: 182.42,171.78 179.18,171.78 v1(178.79,172.17)
IO-BANK2_95: length 6.4
  TOP w0.127: U1.H12 v1(174.79,171.37)
  SIG3 w0.127: v1(174.79,171.37) 174.32,171.84 174.32,177.01
IO-BANK2_96: length 6.2
  TOP w0.127: U1.H15 v1(177.19,171.37)
  SIG2 w0.127: 182.7,170.98 177.58,170.98 v1(177.19,171.37)
IO-BANK4_1: length 1.2
  TOP w0.127: U1.H1 164.39,170.97
IO-BANK4_2: length 2.2
  TOP w0.127: 164.39,171.37 165.99,171.37 U1.H2
IO-BANK4_3: length 1.2
  TOP w0.127: U1.J1 164.39,170.17
IO-BANK4_4: length 2.2
  TOP w0.127: 164.39,170.57 165.99,170.57 U1.J2
IO-BANK4_5: length 2.8
  TOP w0.127: U1.J3 v1(166.79,170.57)
  SIG1 w0.127: v1(166.79,170.57) 164.57,170.57
IO-BANK4_6: length 3.8
  TOP w0.127: U1.J4 v1(167.59,170.57)
  SIG1 w0.127: v1(167.59,170.57) 167.2,170.18 164.57,170.18
IO-BANK4_7: length 4.7
  TOP w0.127: U1.J6 v1(169.19,170.57)
  SIG2 w0.127: v1(169.19,170.57) 168.8,170.97 165.2,170.97
IO-BANK4_8: length 6.3
  TOP w0.127: U1.J7 v1(169.99,170.57)
  SIG3 w0.127: 164.41,170.18 169.6,170.18 v1(169.99,170.57)
IO-BANK4_9: length 7
  TOP w0.127: U1.J8 v1(170.79,170.57)
  SIG3 w0.127: v1(170.79,170.57) 170.4,170.97 170.4,176.81
IO-BANK4_10: length 8.5
  TOP w0.127: U1.J9 v1(171.59,170.57)
  SIG3 w0.127: 173.94,176.73 173.94,171.53 173.38,170.97 171.98,170.97 v1(171.59,170.57)
IO-BANK4_11: length 1.2
  TOP w0.127: U1.K1 164.39,169.37
IO-BANK4_12: length 3
  TOP w0.127: U1.K3 v1(166.79,169.77)
  SIG1 w0.127: 164.52,169.38 166.4,169.38 v1(166.79,169.77)
IO-BANK4_13: length 3.3
  TOP w0.127: U1.K4 v1(167.59,169.77)
  SIG2 w0.127: 165.07,170.18 167.18,170.18 v1(167.59,169.77)
IO-BANK4_14: length 4
  TOP w0.127: U1.K5 v1(168.39,169.77)
  SIG2 w0.127: v1(168.39,169.77) 168,169.38 165.13,169.38
IO-BANK4_15: length 5.4
  TOP w0.127: U1.K6 v1(169.19,169.77)
  SIG2 w0.127: v1(169.19,169.77) 168.78,169.37 168.78,168.78 168.58,168.58 165.18,168.58
IO-BANK4_16: length 7.2
  TOP w0.127: U1.K8 v1(170.79,169.77)
  SIG3 w0.127: 164.36,169.38 170.4,169.38 v1(170.79,169.77)
IO-BANK4_17: length 9
  TOP w0.127: U1.K9 v1(171.59,169.77)
  SIG3 w0.127: 164.34,168.76 165.84,168.76 166.29,168.3 170.81,168.3 171.2,168.68 171.2,169.38 v1(171.59,169.77)
